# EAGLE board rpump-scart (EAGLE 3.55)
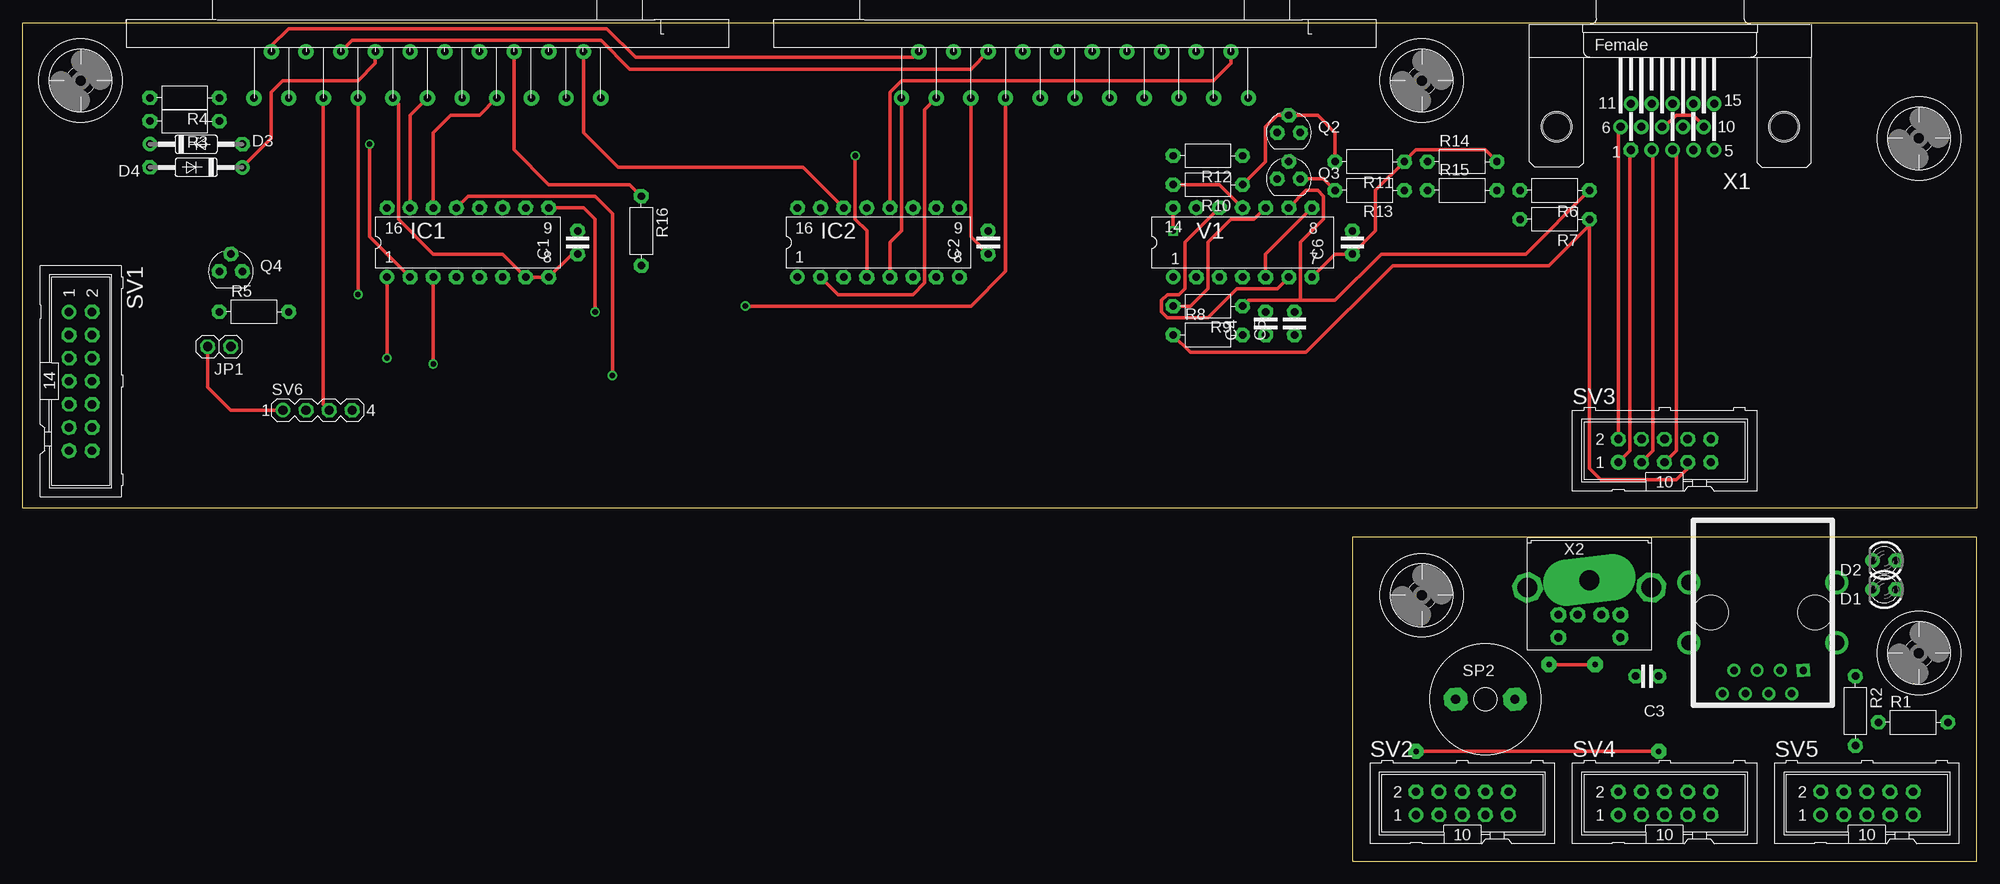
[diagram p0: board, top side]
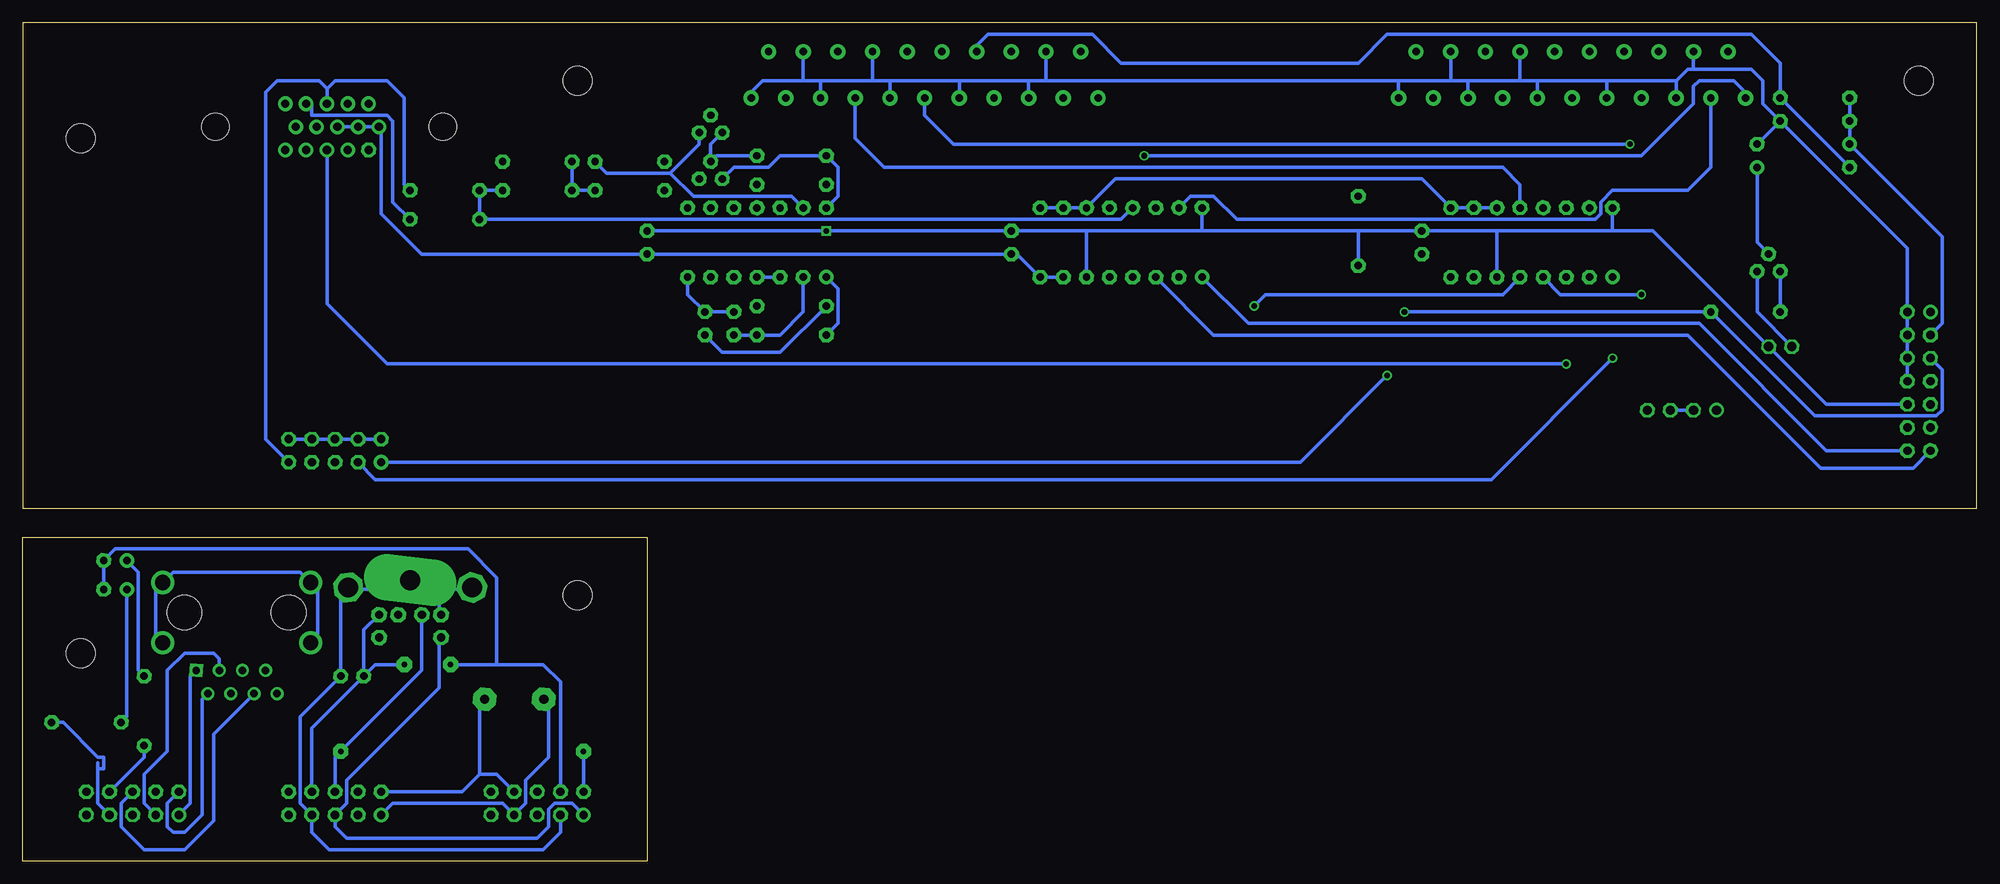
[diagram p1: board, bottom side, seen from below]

Size 214.63 x 92.08 mm. Coordinates in mm from the lower left corner, seen from the top.
Outline: 214.63,92.08 0,92.08 0,38.73 214.63,38.73 214.63,92.08
Outline: 208.28,92.08 214.63,92.08
Outline: 214.63,0 214.63,35.56 146.05,35.56 146.05,0 214.63,0
Copper layers used: Top, Bottom
tRestrict: 4 lines

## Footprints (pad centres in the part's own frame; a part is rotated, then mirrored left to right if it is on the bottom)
2,5 = drill 0.813 pad 1.6 octagon:  -1.27,0;  1.27,0
45 = drill 1.676 pad 2.54 round: ELD1 -8.128,2.032; ELD2 -8.128,-4.572; ELD3 8.128,2.032; ELD4 8.128,-4.572 | drill 0.813 pad 1.422 square:  -4.445,5.08 | drill 0.813 pad 1.422 round:  -3.175,7.62;  -1.905,5.08;  -0.635,7.62;  0.635,5.08;  1.905,7.62;  3.175,5.08;  4.445,7.62 | hole 3.81: -5.715,-1.27; 5.715,-1.27
D3 = drill 0.813 pad 1.6 octagon:  -1.27,0 | drill 0.813 pad 1.6 round:  1.27,0
35Z10 = drill 0.813 pad 1.6 round:  -5.08,0 | drill 0.813 pad 1.6 octagon:  5.08,0
35-10 = drill 0.813 pad 1.6 round:  -5.08,0 | drill 0.813 pad 1.6 octagon:  5.08,0
L16 = drill 0.813 pad 1.6 round:  -8.89,-3.81 | drill 0.813 pad 1.6 octagon:  -6.35,-3.81;  -3.81,-3.81;  -1.27,-3.81;  1.27,-3.81;  3.81,-3.81;  6.35,-3.81;  8.89,-3.81;  8.89,3.81;  6.35,3.81;  3.81,3.81;  1.27,3.81;  -1.27,3.81;  -3.81,3.81;  -6.35,3.81;  -8.89,3.81
02 = drill 1.016 pad 1.6 octagon:  -1.27,0;  1.27,0
T54A = drill 0.813 pad 1.6 octagon:  -1.27,0;  0,1.905;  1.27,0
T54C = drill 0.813 pad 1.6 octagon:  -1.27,0;  0,1.905;  1.27,0
7,5 = drill 0.813 pad 1.6 octagon:  -3.81,0;  3.81,0
60P = drill 1.016 pad 2.54 octagon:  -3.251,0;  3.251,0
14 = drill 0.914 pad 1.6 round:  -7.62,-1.27 | drill 0.914 pad 1.6 octagon:  -7.62,1.27;  -5.08,-1.27;  -5.08,1.27;  -2.54,-1.27;  -2.54,1.27;  0,-1.27;  0,1.27;  2.54,-1.27;  2.54,1.27;  5.08,-1.27;  5.08,1.27;  7.62,-1.27;  7.62,1.27
10 = drill 0.914 pad 1.6 round:  -5.08,-1.27 | drill 0.914 pad 1.6 octagon:  -5.08,1.27;  -2.54,-1.27;  -2.54,1.27;  0,-1.27;  0,1.27;  2.54,-1.27;  2.54,1.27;  5.08,-1.27;  5.08,1.27
04-1 = drill 1.016 pad 1.6 round:  -3.81,0 | drill 1.016 pad 1.6 octagon:  -1.27,0;  1.27,0;  3.81,0
ART = drill 0.813 pad 1.676 round:  -34.29,0;  -30.48,0;  -26.67,0;  -22.86,0;  -19.05,0;  -15.24,0;  -11.43,0;  -7.62,0;  -3.81,0;  0,0;  -36.195,-5.08;  -32.385,-5.08;  -28.575,-5.08;  -24.765,-5.08;  -20.955,-5.08;  -17.145,-5.08;  -13.335,-5.08;  -9.525,-5.08;  -5.715,-5.08;  -1.905,-5.08;  -38.1,0
3,2S = hole 3.2: 0,0
L14 = drill 0.813 pad 1.6 round:  -7.62,-3.81 | drill 0.813 pad 1.6 octagon:  -5.08,-3.81;  -2.54,-3.81;  0,-3.81;  2.54,-3.81;  5.08,-3.81;  7.62,-3.81;  7.62,3.81;  5.08,3.81;  2.54,3.81;  0,3.81;  -2.54,3.81;  -5.08,3.81;  -7.62,3.81
F15H = drill 0.9 pad 1.6 round:  -3.672,0;  -1.386,0;  0.9,0;  3.186,0;  5.472,0;  -4.815,2.54;  -2.529,2.54;  -0.243,2.54;  2.043,2.54;  -4.815,-2.54;  -2.529,-2.54;  -0.243,-2.54;  2.043,-2.54;  4.329,-2.54 | drill 0.9 pad 1.6 octagon:  4.329,2.54 | hole 3: -12.5,0; 12.5,0
NI-6 = drill 0.9 pad 1.676 octagon:  1.3,-8.5;  -1.3,-8.5;  3.4,-8.5;  -3.4,-8.5;  3.4,-11;  -3.4,-11 | drill 2.184 pad 5.08 long:  0,-4.7 | drill 2.184 pad 2.8 octagon:  -6.8,-5.5;  6.8,-5.5

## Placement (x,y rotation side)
C1  100n  [2,5]  60.96,67.95 90 top
C2  100n  [2,5]  106.05,67.95 90 top
C3  100n  [2,5]  178.44,20.32 180 top
C4  2,2u  [2,5]  136.53,59.05 90 top
C5  2,2u  [2,5]  139.7,59.05 90 top
C6  100n  [2,5]  146.05,67.95 90 top
CON1  RJ45  [45]  191.13,26.03 180 top
D1  LED3  [D3]  204.47,29.84 180 top
D2  LED3  [D3]  204.47,33.02 180 top
D3  ZPD  [35Z10]  19.05,78.74 0 top
D4  1N4148  [35-10]  19.05,76.2 180 top
IC1  4053  [L16]  48.9,67.95 0 top
IC2  4053  [L16]  93.98,67.95 0 top
JP1  PINHD-1X2  [02]  21.59,56.51 180 top
Q2  BC547  [T54A]  139.06,80.01 0 top
Q3  BC547  [T54A]  139.06,74.93 0 top
Q4  BF245  [T54C]  22.86,64.77 0 top
R1  820  [7,5]  207.65,15.24 0 top
R2  820  [7,5]  201.29,16.51 270 top
R3  RESEU-7,5  [7,5]  17.78,81.28 180 top
R4  680  [7,5]  17.78,83.82 180 top
R5  2k2  [7,5]  25.4,60.32 0 top
R6  RESEU-7,5  [7,5]  168.28,73.66 180 top
R7  RESEU-7,5  [7,5]  168.28,70.48 180 top
R8  2k2  [7,5]  130.18,57.79 0 top
R9  2k2  [7,5]  130.18,60.96 180 top
R10  2k2  [7,5]  130.18,74.3 180 top
R11  2k2  [7,5]  147.96,76.84 180 top
R12  2k2  [7,5]  130.18,77.47 180 top
R13  47  [7,5]  147.96,73.66 180 top
R14  47  [7,5]  158.12,76.84 0 top
R15  47  [7,5]  158.12,73.66 0 top
R16  120  [7,5]  67.94,69.22 270 top
SP2  AL60P  [60P]  160.66,17.78 0 top
SV1  ML14E  [14]  6.35,52.7 270 top
SV2  ML10  [10]  158.12,6.35 0 top
SV3  ML10  [10]  180.34,45.09 0 top
SV4  ML10  [10]  180.34,6.35 0 top
SV5  ML10  [10]  202.56,6.35 0 top
SV6  MA04-1  [04-1]  32.38,49.53 0 top
U$1  SCART  [ART]  96.52,83.82 180 top
U$2  [3,2S]  6.35,85.73 0 top
U$3  SCART  [ART]  25.4,83.82 180 top
U$4  [3,2S]  153.67,85.73 0 top
U$7  [3,2S]  208.28,79.38 0 top
U$8  [3,2S]  208.28,22.86 0 top
U$9  [3,2S]  153.67,29.21 0 top
V1  74HC86  [L14]  133.99,67.95 0 top
X1  HF15H  [F15H]  180.97,80.65 180 top
X2  MINI-6  [NI-6]  172.09,35.56 0 top

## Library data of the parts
C1-C6 R1-R16 = DISCRETE
CON1 U$1 U$3 = con-pc
D1 D2 = led
D3 D4 = DIODE
IC1 IC2 V1 = 40xx
JP1 = PINHEAD
Q2-Q4 = TRANS-SM
SP2 = buzzer
SV1-SV5 = CON-ML
SV6 = con-lstb
U$2 U$4 U$7-U$9 = HOLES
X1 = subd
X2 = HIRSCHM

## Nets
+5V: C1. C2. C6. IC1. IC2. JP1. Q3. R12. R16. SV1. V1.
+5V_KEYB: C3. D1. D2. SV2. SV4. X2.
+12V: JP1. Q4. SV6.
BLAU: IC1. SV3. X1.
CLOCK: SV2. SV4. X2.
DATA: SV2. SV4. X2.
GND: C1. C2. C4. C5. C6. D3. IC1. IC2. Q2. R3. R11. R14. SV1. SV3. SV6. U$1. U$3. V1. X1.
GND_KEYB: C3. SV2. SV4. X2.
GND_NET: CON1.ELD1 CON1.ELD2 CON1.ELD3 CON1.ELD4
GRUEN: IC1. SV3. X1.
H: R6. R9. SV3. V1. X1.
N$1: R1. SV5.
N$2: R2. SV5.
N$4: C4. R8. V1.
N$5: SP2. SV2. SV4.
N$6: SP2. SV2. SV4.
N$7: D2. R2.
N$8: D1. R1.
N$9: IC2. U$3.
N$10: IC2. U$3.
N$11: IC1. U$3.
N$12: IC1. U$3.
N$13: IC1. U$3.
N$14: IC2. U$3.
N$15: IC2. SV1.
N$16: IC2. SV1.
N$17: C5. R9. V1.
N$18: Q4. R5.
N$19: D4. Q4. U$3.
N$20: D4. R4. U$1.
N$21: D3. R3. R4. SV1.
N$22: IC1. U$1.
N$23: IC1. U$1.
N$24: IC1. U$1.
N$25: IC2. U$1.
N$26: IC2. U$1.
N$27: IC2. U$1.
N$28: IC2. R6. R7. R15.
N$29: Q2. R10. R11.
N$30: IC1. IC2. R5. SV1.
N$31: R16. U$3.
N$32: V1.
N$33: V1.
N$34: V1.
N$35: Q2. Q3. R12.
N$36: U$1.
N$37: Q3. R13.
N$38: R13. R14. R15.
N$39: U$1. U$3.
N$40: U$1. U$3.
N$41: U$1.
N$42: R10. V1.
N$43: U$1.
N$44: U$1.
N$45: U$3.
N$46: U$3.
N$47: U$3.
ROT: IC1. SV3. X1.
RX+: CON1. SV5.
RX-: CON1. SV5.
TX+: CON1. SV5.
TX-: CON1. SV5.
V: R7. R8. SV3. V1. X1.

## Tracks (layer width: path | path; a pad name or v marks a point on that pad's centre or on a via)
+5V  (via drill 0.61 pad 1.02)
  Top 0.406: v126.36,69.22 V1.
  Bottom 0.406: 7.62,50.16 16.51,50.16 22.86,56.51 35.56,69.22 40.01,69.22 | 52.7,69.22 52.7,64.14 | 52.7,69.22 C1. 67.94,69.22 | 97.79,69.22 97.79,64.14 | 97.79,69.22 C2. v126.36,69.22 C6. | 67.94,69.22 85.09,69.22 | 85.09,69.22 97.79,69.22 | 40.01,69.22 52.7,69.22 | 67.94,69.22 R16. | 137.79,74.93 136.53,76.2 132.72,76.2 131.44,77.47 R12. 125.09,76.2 125.09,73.03 V1. | 85.09,69.22 IC2. | 40.01,69.22 IC1.
+5V_KEYB  (via drill 0.61 pad 1.68)
  Top 0.406: v167.64,21.59 v172.72,21.59
  Bottom 0.406: 162.56,21.59 162.56,31.11 165.74,34.29 204.47,34.29 205.74,33.02 205.74,29.84 | 155.57,7.62 155.57,19.69 157.48,21.59 162.56,21.59 | 182.88,7.62 182.88,14.6 C3. | C3. 177.16,25.4 175.5,27.06 175.49,27.06 | 162.56,21.59 v167.64,21.59 | v172.72,21.59 175.9,21.59 C3.
+12V
  Top 0.406: JP1. 20.32,52.07 22.86,49.53 28.57,49.53
  Bottom 0.406: JP1. 24.13,60.32 Q4.
BLAU  (via drill 0.61 pad 1.02)
  Top 0.406: 180.34,43.81 181.61,45.09 181.61,78.11 181.22,78.11 | v45.09,54.61 45.09,64.14
  Bottom 0.406: v45.09,54.61 174.62,54.61 181.22,61.2 181.22,78.11 181.61,78.11
CLOCK  (via drill 0.61 pad 1.68)
  Top 0.406: v153.03,12.06 v179.71,12.06
  Bottom 0.406: 153.03,7.62 v153.03,12.06 | 180.34,7.62 180.34,11.43 v179.71,12.06 170.81,20.95 170.81,27.03 170.78,27.06
DATA
  Bottom 0.406: 153.03,5.08 154.31,6.35 156.21,6.35 156.84,5.71 156.84,3.81 158.12,2.54 179.07,2.54 180.34,3.81 180.34,5.08 179.07,6.35 179.07,8.89 168.91,19.05 168.91,24.34 168.69,24.56
GND
  Top 0.406: 33.66,49.53 33.02,50.16 33.02,83.82 | 184.65,80.65 184.78,80.65 183.51,81.92 181.61,81.92 180.34,80.65 180.07,80.65 | 175.5,80.65 175.26,80.65 175.26,46.35 | 106.05,66.68 104.14,68.58 104.14,83.82 | 60.96,66.68 60.33,66.68 57.78,64.14 55.24,64.14 52.7,66.68 45.09,66.68 41.27,70.48 41.27,83.19 40.64,83.82 | 141.6,64.14 144.15,66.68 146.05,66.68 148.59,69.22 148.59,73.66 151.76,76.84 153.03,78.11 160.66,78.11 R14.
  Bottom 0.406: 7.62,52.7 7.62,55.24 7.62,57.79 7.62,60.32 7.62,67.31 21.59,81.28 | 33.66,49.53 31.11,49.53 | 40.64,85.73 33.02,85.73 | 33.02,85.73 33.02,83.82 | 40.64,85.73 40.64,83.82 | 48.26,85.73 40.64,85.73 | 48.26,85.73 48.26,83.82 | 55.88,85.73 50.16,85.73 | 50.16,85.73 48.26,85.73 | 55.88,85.73 55.88,83.82 | 63.5,85.73 57.78,85.73 | 57.78,85.73 55.88,85.73 | 63.5,85.73 U$3. | 180.34,80.65 180.07,80.65 177.79,80.65 175.5,80.65 175.26,80.65 175.26,71.12 170.81,66.68 146.05,66.68 106.05,66.68 105.41,66.68 102.87,64.14 100.33,64.14 | 175.26,46.35 177.8,46.35 180.34,46.35 182.88,46.35 SV3. | 104.14,85.73 111.76,85.73 | 111.76,85.73 111.76,83.82 | 104.14,83.82 104.14,85.73 | 111.76,85.73 119.38,85.73 | 119.38,85.73 119.38,83.82 | 119.38,85.73 121.28,85.73 | 121.28,85.73 127,85.73 | 127,85.73 127,83.82 | 127,85.73 128.91,85.73 | 128.91,85.73 133.35,85.73 134.62,84.45 U$1. | 104.14,85.73 102.23,85.73 | 102.23,85.73 63.5,85.73 | 121.28,85.73 121.28,88.9 | 128.91,85.73 128.91,88.9 | 102.23,85.73 102.23,88.9 | 57.78,85.73 57.78,88.9 | 50.16,85.73 50.16,88.9 | 31.11,87 31.11,88.9 | 33.02,85.73 31.75,87 31.11,87 | 21.59,81.28 D3. | 21.59,81.28 23.5,83.19 23.5,85.73 24.77,87 31.11,87 | Q2. 140.34,78.74 143.51,75.56 | 143.51,75.56 150.5,75.56 151.76,76.84 | 128.91,71.76 130.18,73.03 140.97,73.03 143.51,75.56 | C4. C5. 141.6,62.23 141.6,64.14
GND_KEYB
  Bottom 0.406: 155.57,5.08 155.57,3.17 157.48,1.27 180.97,1.27 182.88,3.17 182.88,5.08 184.15,6.35 184.15,15.87 179.71,20.32 179.71,29.24 X2. 178.67,29.84 173.1,29.84 172.09,30.86 171.07,29.84 168.91,29.84 | 168.69,27.06 168.91,27.28 168.91,29.84 | 165.28,30.06 165.5,29.84 168.91,29.84
GND_NET
  Bottom 0.406: CON1.ELD3 182.25,24.77 182.25,29.84 CON1.ELD4 184.15,31.75 198.12,31.75 CON1.ELD2 200.03,29.84 200.03,24.77 CON1.ELD1
GRUEN  (via drill 0.61 pad 1.02)
  Top 0.406: 177.8,43.81 179.07,45.09 179.07,78.11 178.93,78.11 | v40.01,55.24 40.01,64.14
  Bottom 0.406: v40.01,55.24 53.34,41.91 175.9,41.91 177.8,43.81
H
  Top 0.406: 133.99,60.96 134.62,61.59 140.34,61.59 | 140.34,61.59 140.34,67.95 142.88,70.48 142.88,73.03 142.24,73.66 140.97,73.66 139.06,71.76 | 140.34,61.59 144.15,61.59 149.22,66.68 165.1,66.68 172.09,73.66
  Bottom 0.406: 172.09,73.66 172.72,74.3 172.72,83.82 174.62,85.73 180.34,85.73 181.22,84.85 | 185.42,43.81 187.96,46.35 187.96,84.45 186.69,85.73 182.1,85.73 181.22,84.85 | 181.22,84.85 181.22,83.19
N$1
  Bottom 0.406: 205.1,5.08 206.38,6.35 206.38,10.16 | 206.38,10.16 206.38,10.79 | R1. 210.19,15.24 206.38,11.43 205.74,11.43 205.74,10.16 206.38,10.16
N$2
  Bottom 0.406: R2. 201.29,11.43 205.1,7.62
N$4
  Bottom 0.406: 128.91,64.14 128.91,60.32 131.44,57.79 R8. 136.53,57.79
N$5
  Bottom 0.406: 175.26,5.08 173.99,6.35 161.93,6.35 160.66,5.08 159.38,6.35 159.38,8.89 156.84,11.43 156.84,17.22 157.4,17.78
N$6
  Bottom 0.406: 175.26,7.62 166.37,7.62 164.47,9.53 | 164.47,9.53 162.56,9.53 160.66,7.62 | SP2. 164.47,17.22 164.47,9.53
N$7
  Bottom 0.406: D2. 201.93,31.75 201.93,20.95 201.29,20.32
N$8
  Bottom 0.406: D1. 203.2,15.87 203.84,15.24
N$9  (via drill 0.61 pad 1.02)
  Top 0.406: 92.71,64.14 92.71,69.22 91.44,70.48 v91.44,77.47
  Bottom 0.406: v91.44,77.47 36.83,77.47 31.11,83.19 31.11,85.09 30.48,85.73 26.67,85.73 25.4,84.45 25.4,83.82
N$10
  Bottom 0.406: 87.63,71.76 86.36,73.03 83.82,73.03 81.28,70.48 41.91,70.48 41.27,71.12 41.27,72.39 40.01,73.66 31.75,73.66 29.21,76.2 29.21,83.82
N$11  (via drill 0.61 pad 1.02)
  Top 0.406: v36.83,62.23 36.83,83.82
  Bottom 0.406: v36.83,62.23 45.72,62.23 47.62,64.14
N$12
  Top 0.406: 42.55,71.76 42.55,81.92 44.45,83.82
N$13
  Top 0.406: 45.09,71.76 45.09,80.01 46.99,81.92 50.16,81.92 52.07,83.82
N$14
  Top 0.406: 61.59,88.9 61.59,80.01 65.41,76.2 85.72,76.2 90.17,71.76
N$15
  Bottom 0.406: 5.08,45.09 6.99,43.18 17.14,43.18 31.75,57.79 83.82,57.79 90.17,64.14
N$16
  Bottom 0.406: SV1. 16.51,45.09 30.48,59.05 80.01,59.05 85.09,64.14
N$17
  Top 0.406: R9. 128.27,60.96 130.18,62.87 130.18,67.95 132.72,70.48 135.25,70.48 136.53,71.76
  Bottom 0.406: 139.7,57.79 137.79,55.88 131.44,55.88 R9.
N$18
  Bottom 0.406: 21.59,60.32 21.59,64.77
N$19
  Top 0.406: 38.73,88.9 38.73,87.63 36.83,85.73 28.57,85.73 27.3,84.45 27.3,79.38 24.13,76.2
  Bottom 0.406: 22.86,66.68 24.13,67.95 24.13,76.2
N$20
  Bottom 0.406: 109.86,88.9 109.86,89.54 108.58,90.81 97.16,90.81 93.98,87.63 67.94,87.63 64.77,90.81 24.77,90.81 21.59,87.63 21.59,83.82 D4.
N$21
  Bottom 0.406: 5.08,57.79 3.81,59.05 3.81,68.58 13.97,78.74 R3. R4.
N$22
  Bottom 0.406: 50.16,71.76 50.16,74.3 52.07,76.2 120.02,76.2 123.19,79.38 123.19,83.82
N$23  (via drill 0.61 pad 1.02)
  Top 0.406: v38.1,78.74 38.1,68.58 42.55,64.14
  Bottom 0.406: v38.1,78.74 112.39,78.74 115.57,81.92 115.57,83.82
N$24  (via drill 0.61 pad 1.02)
  Top 0.406: v79.38,60.96 104.14,60.96 107.95,64.77 107.95,83.82
  Bottom 0.406: v79.38,60.96 78.11,62.23 52.07,62.23 50.16,64.14
N$25
  Top 0.406: 87.63,64.14 89.53,62.23 97.79,62.23 99.06,63.5 99.06,82.55 100.33,83.82
N$26
  Top 0.406: 95.25,64.14 95.25,67.95 96.52,69.22 96.52,83.82
N$27
  Top 0.406: 95.25,71.76 95.25,84.45 96.52,85.73 130.81,85.73 132.72,87.63 132.72,88.9
N$28
  Bottom 0.406: 92.71,71.76 93.98,70.48 R7. R6. R15.
N$29
  Top 0.406: 133.99,74.3 136.53,76.84 136.53,80.65 137.79,81.92 139.06,81.92 142.24,81.92 144.15,80.01 R11.
N$30  (via drill 0.61 pad 1.02)
  Top 0.406: v62.87,60.32 62.87,70.48 61.59,71.76 57.78,71.76
  Bottom 0.406: 5.08,55.24 3.81,53.97 3.81,49.53 4.45,48.89 17.78,48.89 R5. v62.87,60.32 | 52.7,71.76 55.24,71.76 57.78,71.76 60.96,74.93 94.61,74.93 97.79,71.76 100.33,71.76 102.87,71.76
N$31
  Top 0.406: 67.94,73.03 66.67,74.3 57.78,74.3 53.98,78.11 53.98,88.9
N$32
  Bottom 0.406: 131.44,64.14 133.99,64.14
N$33
  Top 0.406: 141.6,71.76 136.53,66.68 136.53,64.14
N$34
  Top 0.406: 131.44,71.76 127.64,67.95 127.64,62.87 127,62.23 125.73,62.23 125.09,61.59 125.09,60.32 125.73,59.69 130.18,59.69 133.35,62.87 137.79,62.87 139.06,64.14
N$35
  Bottom 0.406: 137.79,80.01 139.06,78.74 139.06,76.84 138.43,77.47 133.99,77.47
N$37
  Top 0.406: R13. 142.88,74.93 Q3.
N$38
  Bottom 0.406: 151.76,73.66 154.31,73.66 154.31,76.84
N$39
  Top 0.406: 27.3,88.9 27.3,89.54 29.21,91.44 64.14,91.44 67.31,88.27 97.79,88.27 98.42,88.9
N$40
  Top 0.406: 106.05,88.9 104.14,87 66.67,87 63.5,90.17 36.2,90.17 34.92,88.9
N$42
  Top 0.406: 133.99,71.76 131.44,74.3 R10.
ROT  (via drill 0.61 pad 1.02)
  Top 0.406: 175.26,43.81 176.53,45.09 176.53,78.11 176.65,78.11 | 47.62,71.76 48.9,73.03 62.87,73.03 64.77,71.12 v64.77,53.34
  Bottom 0.406: 175.26,43.81 74.3,43.81 v64.77,53.34
RX+
  Bottom 0.406: 200.03,5.08 201.29,6.35 201.29,9.53 198.75,12.06 198.75,20.95 196.85,22.86 193.68,22.86 193.04,22.23 193.04,20.95
RX-
  Bottom 0.406: 202.56,7.62 203.84,6.35 203.84,3.81 201.29,1.27 196.85,1.27 193.68,4.44 193.68,13.97 189.23,18.41
TX+
  Bottom 0.406: 197.49,5.08 196.22,6.35 196.22,20.32 195.58,20.95
TX-
  Bottom 0.406: 197.49,7.62 198.75,6.35 198.75,3.81 198.12,3.17 196.85,3.17 194.94,5.08 194.94,17.78 194.31,18.41
V
  Top 0.406: 182.88,43.81 182.88,43.18 181.61,41.91 173.35,41.91 172.09,43.18 172.09,70.48 172.09,69.85 167.64,65.41 150.5,65.41 140.97,55.88 128.27,55.88 126.36,57.79
  Bottom 0.406: 183.5,83.19 182.88,83.19 182.88,81.92 174.62,81.92 173.99,81.28 173.99,72.39 172.09,70.48 | 126.36,64.14 125.09,62.87 125.09,59.05 126.36,57.79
